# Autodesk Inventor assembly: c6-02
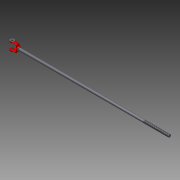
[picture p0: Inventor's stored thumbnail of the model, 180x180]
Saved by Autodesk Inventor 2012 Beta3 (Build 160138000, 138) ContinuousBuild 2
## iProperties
Created: 2010-12
Part Number: c6-02
Document SubType Name: Assembly
Designer: Beta-8540w
Author: Beta-8540w
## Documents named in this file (3)
- C:\Inventor 2012 Essentials\Assemblies\Chapter 6\c6-02.iam
- C:\Inventor 2012 Essentials\Parts\Chapter 6\c6-09.ipt
- C:\Inventor 2012 Essentials\Parts\Chapter 6\c6-10.ipt
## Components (2 placed, 2 different names)
1. c6-09:1
2. c6-10:1 — Insert:1
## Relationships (1: Insert 1)
- Insert:1: c6-10:1
